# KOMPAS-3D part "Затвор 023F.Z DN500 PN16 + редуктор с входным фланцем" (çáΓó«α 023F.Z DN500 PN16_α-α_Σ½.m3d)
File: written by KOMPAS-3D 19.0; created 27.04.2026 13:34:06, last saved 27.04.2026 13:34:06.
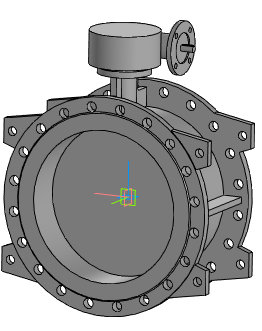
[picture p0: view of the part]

Document properties: Полное имя файла: Затвор 023F.Z DN500 PN16_р-р_фл.m3d

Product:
- Part/product: Затвор 023F.Z DN500 PN16 + редуктор с входным фланцем
    Масса: 313.644
  - Component [detail]: Затвор 023F.Z DN500 PN16 под исполнительный механизм  | Масса: 268.02; source file: ..\..\Затвор 023F.Z DN200-DN1600 под исполнительный механизм\Затвор 023F.Z DN500 PN16 под исполнительный механизм.m3d
  - Component [detail]: Редуктор 023F.Z 350(16)-600(10)_450(16)-500(16) фланец  | Масса: 45.624; source file: ..\..\Редукторы\Редуктор 023F.Z 350(16)-600(10)_450(16)-500(16) фланец.m3d

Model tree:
1. Элемент выдавливания:2  (with: Элемент выдавливания:17, Элемент выдавливания:1, Элемент выдавливания:16, Элемент вращения:1, Элемент вращения:2)

Referenced files in Z:\3.Личные\kachalov\3d для проектировщиков\1.7 Тип 023F.Z Затвор дисковый поворотный фланцевый с двумя эксцентриками\Редукторы\: Редуктор 023F.Z 350(16)-600(10)_450(16)-500(16) фланец.m3d
Referenced files in Z:\3.Личные\kachalov\3d для проектировщиков\1.7 Тип 023F.Z Затвор дисковый поворотный фланцевый с двумя эксцентриками\Затвор 023F.Z DN200-DN1600 под исполнительный механизм\: Затвор 023F.Z DN500 PN16 под исполнительный механизм.m3d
